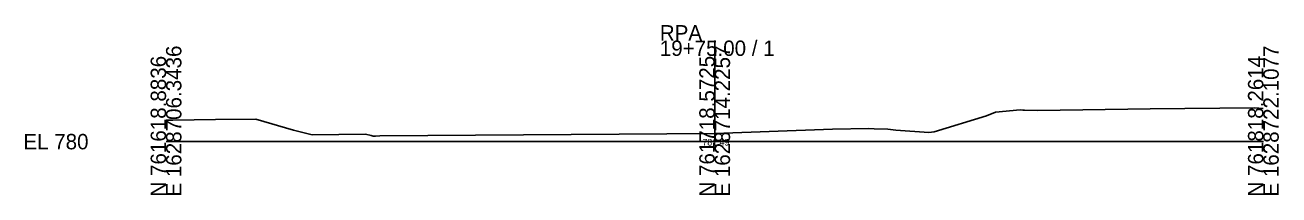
# Model space of a CAD drawing. Extents: x -26 to 203, y 990 to 7517.
# Drawn here: x -25.7 to 202.8, y 3490.3 to 3521.2 of the extents above; entities that cross this region are included whole.
import ezdxf

# ---------------------------------------------------------------- set-up
doc = ezdxf.new("R2010")
doc.units = 0
for name, color, linetype in [('Exist Cross Section Cell', 7, 'Continuous'), ('Exist XS Center Line Elevation Label', 7, 'Continuous'), ('Exist XS Ground Line', 7, 'Continuous')]:
    doc.layers.add(name, color=color, linetype=linetype)

msp = doc.modelspace()

# ---------------------------------------------------------------- linework, layer by layer
at = {"layer": 'Exist Cross Section Cell'}
for p, q in [((100, 3500), (100, 3518.4)), ((0, 3500), (100, 3500)), ((100, 3500), (200, 3500))]:
    msp.add_line(p, q, dxfattribs=at)
at = {"layer": 'Exist XS Ground Line'}
for p, q in [((151.19, 3505.38), (155.66, 3505.78)), ((155.66, 3505.78), (156.19, 3505.72)), ((156.19, 3505.72), (156.49, 3505.7)), ((156.49, 3505.7), (158.88, 3505.69)), ((158.88, 3505.69), (179.36, 3505.98)), ((179.36, 3505.98), (198.4, 3506.13)), ((198.4, 3506.13), (199.94, 3506.04)), ((0, 3503.89), (1.22, 3503.89)), ((1.22, 3503.89), (8.99, 3504.04)), ((8.99, 3504.04), (16.35, 3504.08)), ((16.35, 3504.08), (23.26, 3502.11)), ((140, 3501.79), (149.55, 3504.68)), ((149.55, 3504.68), (151.19, 3505.38)), ((23.26, 3502.11), (26.66, 3501.26)), ((26.66, 3501.26), (31.51, 3501.29)), ((31.51, 3501.29), (36.36, 3501.34)), ((36.36, 3501.34), (37.39, 3501.09)), ((38.95, 3501.05), (100, 3501.49)), ((100, 3501.49), (121.46, 3502.27)), ((121.46, 3502.27), (128.07, 3502.41)), ((128.07, 3502.41), (129.04, 3502.35)), ((129.04, 3502.35), (131.58, 3502.25)), ((131.58, 3502.25), (132.99, 3502.11)), ((132.99, 3502.11), (139.06, 3501.65)), ((139.06, 3501.65), (140, 3501.79)), ((37.39, 3501.09), (37.73, 3500.97)), ((37.73, 3500.97), (38.16, 3501)), ((38.16, 3501), (38.95, 3501.05))]:
    msp.add_line(p, q, dxfattribs=at)

# ---------------------------------------------------------------- texts
at = {"layer": 'Exist Cross Section Cell'}
for s, p in [('RPA', (90, 3518.4)), ('19+75.00 / 1', (90, 3515.6)), ('EL 780', (-26, 3498.6))]:
    msp.add_text(s, height=2.8, dxfattribs=at).set_placement(p)
for s, p in [('E 1628706.3436', (2.8, 3490)), ('E 1628714.2257', (102.8, 3490)), ('E 1628722.1077', (202.8, 3490)), ('N 761618.8836', (0, 3490)), ('N 761718.5725', (100, 3490)), ('N 761818.2614', (200, 3490))]:
    msp.add_text(s, height=2.8, rotation=90, dxfattribs=at).set_placement(p)
at = {"layer": 'Exist XS Center Line Elevation Label'}
msp.add_text('781.49', height=1.2, dxfattribs=at).set_placement((97.76, 3499.29))

doc.saveas('drawing.dxf')
